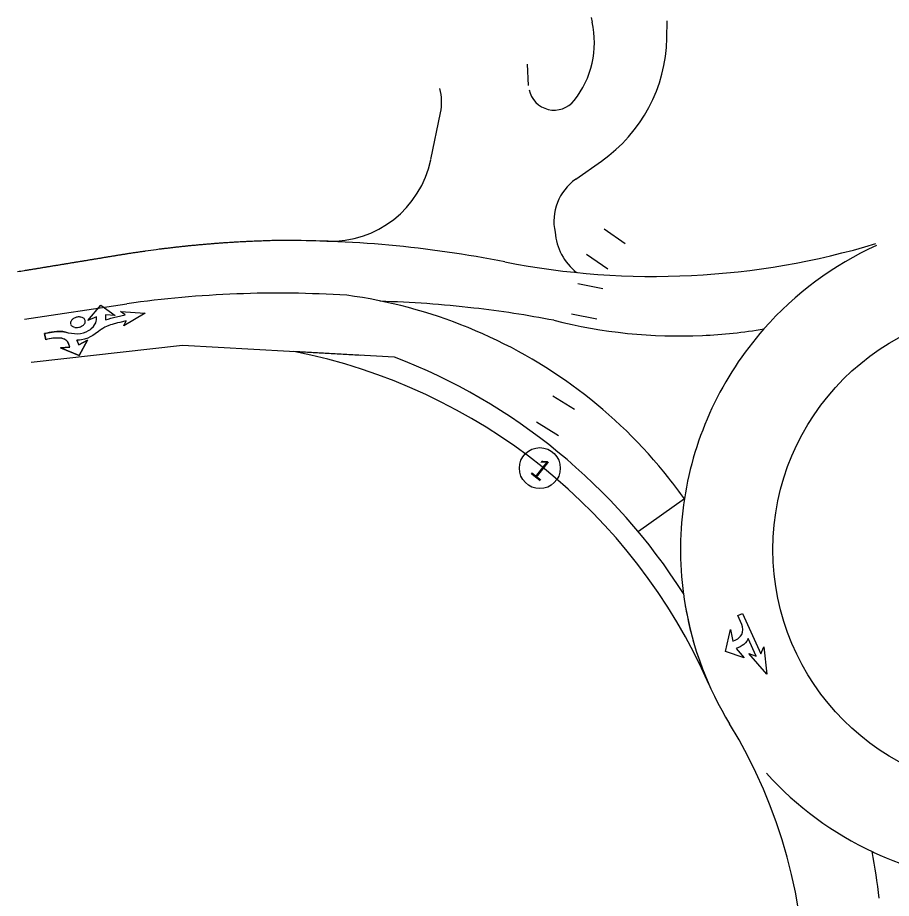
# Model space of a CAD drawing. Extents: x 553958 to 562499, y 493978 to 516388.
# Drawn here: x 561594.7 to 561765, y 497732.6 to 497904.2 of the extents above; entities that cross this region are included whole.
import ezdxf

# ---------------------------------------------------------------- set-up
doc = ezdxf.new("R2010")
doc.units = 0
for name, color, linetype in [('Exist Horizontal Alignment', 7, 'Continuous'), ('Prop Conc Shoulder Berm Gutter', 7, 'Continuous'), ('Prop Drainage Structure Gutter Shoulder Berm Label', 7, 'Continuous'), ('Prop DSN Text', 7, 'Continuous'), ('Prop EOT', 7, 'Continuous'), ('Prop Horizontal Alignment Tick Label', 7, 'Continuous'), ('Prop SS Cut Line', 7, 'Continuous'), ('Prop SS Fill Line', 7, 'Continuous'), ('Prop SS Transition Line', 7, 'Continuous'), ('Scratch_Level_4', 7, 'Continuous'), ('Sheet Plot Border Inside CELL', 7, 'Continuous'), ('Sheet Plot Border Outside CELL', 7, 'Continuous')]:
    doc.layers.add(name, color=color, linetype=linetype)

msp = doc.modelspace()

# ---------------------------------------------------------------- linework, layer by layer
at = {"layer": 'Exist Horizontal Alignment'}
msp.add_line((561597.34, 497837.09), (561626.82, 497840.36), dxfattribs=at)
msp.add_circle((561788.88, 497800.56), 47, dxfattribs=at)
msp.add_spline([(561619.61, 497858.68), (561619.59, 497858.67), (561618.91, 497858.58), (561618.23, 497858.48), (561617.55, 497858.38), (561616.87, 497858.27), (561616.19, 497858.17), (561615.51, 497858.06), (561614.83, 497857.95), (561614.17, 497857.85), (561613.52, 497857.74), (561612.87, 497857.63), (561612.22, 497857.52), (561611.57, 497857.42), (561610.93, 497857.31), (561610.28, 497857.2), (561609.63, 497857.1), (561608.98, 497856.99), (561608.33, 497856.88), (561607.68, 497856.78), (561607.03, 497856.67), (561606.38, 497856.56), (561605.73, 497856.46), (561605.09, 497856.35), (561604.44, 497856.24), (561603.79, 497856.14), (561603.14, 497856.03), (561602.49, 497855.92), (561601.84, 497855.82), (561601.19, 497855.71), (561600.54, 497855.6), (561599.9, 497855.5), (561599.25, 497855.39), (561598.6, 497855.28), (561597.95, 497855.18), (561597.3, 497855.07), (561596.65, 497854.96), (561596, 497854.86), (561594.71, 497854.64)], degree=3, dxfattribs=at)
at = {"layer": 'Prop Conc Shoulder Berm Gutter'}
msp.add_lwpolyline([(561724.64, 497810.44), (561715.66, 497804.08), (561715.66, 497804.08)], dxfattribs=at)
at = {"layer": 'Prop Drainage Structure Gutter Shoulder Berm Label'}
msp.add_lwpolyline([(561735.96, 497788.15), (561739.51, 497780.24), (561740.09, 497781.6), (561740.72, 497776.31), (561737.2, 497780.3), (561738.59, 497779.83), (561737.05, 497783.28), (561736.78, 497782.75), (561736.55, 497782.42), (561736.2, 497782.09), (561735.9, 497781.87), (561735.5, 497781.62), (561734.74, 497781.3), (561736.27, 497779.52), (561732.63, 497780.72), (561733.62, 497785), (561734.09, 497782.74), (561734.68, 497783.02), (561735.02, 497783.19), (561735.33, 497783.44), (561735.57, 497783.74), (561735.8, 497784.05), (561735.96, 497784.51), (561736.01, 497785.01), (561735.97, 497785.5), (561735.83, 497786.01), (561735.04, 497787.74)], close=True, dxfattribs=at)
msp.add_lwpolyline([(561735.96, 497788.15), (561739.51, 497780.24), (561740.09, 497781.6), (561740.72, 497776.31), (561737.2, 497780.3), (561738.59, 497779.83), (561737.05, 497783.28), (561736.78, 497782.75), (561736.55, 497782.42), (561736.2, 497782.09), (561735.9, 497781.87), (561735.5, 497781.62), (561734.74, 497781.3), (561736.27, 497779.52), (561732.63, 497780.72), (561733.62, 497785), (561734.09, 497782.74), (561734.68, 497783.02), (561735.02, 497783.19), (561735.33, 497783.44), (561735.57, 497783.74), (561735.8, 497784.05), (561735.96, 497784.51), (561736.01, 497785.01), (561735.97, 497785.5), (561735.83, 497786.01), (561735.04, 497787.74)], close=True, dxfattribs=at)
at = {"layer": 'Prop DSN Text'}
msp.add_circle((561696.46, 497816.43), 3.99, dxfattribs=at)
at = {"layer": 'Prop EOT'}
msp.add_lwpolyline([(561614.75, 497846.96), (561619.53, 497846.6), (561615.4, 497844.17), (561615.88, 497845.09), (561614.62, 497844.8), (561614.2, 497844.7), (561613.78, 497844.59), (561613.53, 497844.53), (561613.13, 497844.42), (561612.78, 497844.32), (561612.45, 497844.21), (561612.04, 497844.04), (561611.73, 497843.89), (561611.5, 497843.76), (561611.33, 497843.65), (561611.02, 497843.45), (561610.78, 497843.28), (561610.44, 497843.01), (561609.85, 497842.56), (561609.39, 497842.27), (561608.83, 497841.98), (561608.36, 497841.77), (561607.73, 497841.56), (561607.16, 497841.42), (561606.75, 497841.36), (561606.26, 497841.32), (561606.39, 497841.05), (561606.53, 497840.71), (561606.63, 497840.42), (561608.31, 497841.36), (561606.67, 497838.34), (561603.08, 497839.86), (561604.9, 497840.01), (561604.77, 497840.39), (561604.68, 497840.59), (561604.61, 497840.76), (561604.52, 497840.92), (561604.42, 497841.06), (561604.25, 497841.27), (561604.13, 497841.36), (561603.9, 497841.51), (561603.77, 497841.57), (561603.59, 497841.64), (561603.37, 497841.7), (561603.13, 497841.73), (561602.95, 497841.75), (561602.58, 497841.76), (561602.26, 497841.76), (561601.91, 497841.74), (561601.55, 497841.71), (561601.25, 497841.67), (561600.85, 497841.6), (561600.51, 497841.52), (561600.2, 497841.44), (561599.92, 497842.64), (561600.29, 497842.71), (561601.04, 497842.85), (561601.8, 497842.97), (561602.58, 497843.04), (561603.13, 497843.03), (561603.73, 497842.98), (561604.17, 497842.9), (561604.57, 497842.8), (561605.18, 497842.69), (561605.8, 497842.62), (561606.37, 497842.6), (561606.94, 497842.66), (561607.57, 497842.81), (561608.07, 497843), (561608.5, 497843.22), (561608.88, 497843.45), (561609, 497843.57), (561609.47, 497844.01), (561609.72, 497844.32), (561609.95, 497844.73), (561610.04, 497845.04), (561610.07, 497845.32), (561610.06, 497845.87), (561608.36, 497845.2), (561610.9, 497848.15), (561613.71, 497846.16), (561611.8, 497846.26), (561611.85, 497845.95), (561611.86, 497845.7), (561611.85, 497845.42), (561611.83, 497845.29), (561612.33, 497845.47), (561612.88, 497845.64), (561613.38, 497845.77), (561614, 497845.91), (561615.65, 497846.3)], close=True, dxfattribs=at)
for points in [[(561599.92, 497842.64), (561600.2, 497841.44)], [(561604.9, 497840.01), (561603.08, 497839.86), (561606.67, 497838.34), (561608.31, 497841.36), (561606.63, 497840.42)]]:
    msp.add_lwpolyline(points, dxfattribs=at)
for centre, radius, start, end in [((561606.31, 497844.35), 1.4, 125.8391, 148.5686), ((561606.67, 497843.85), 2.01, 117.8542, 125.8391), ((561606.71, 497843.77), 2.1, 105.1551, 117.8542), ((561606.68, 497843.89), 1.98, 103.1165, 105.1551), ((561606.68, 497843.89), 1.98, 101.0779, 103.1165), ((561606.7, 497843.77), 2.1, 88.3788, 101.0779), ((561606.7, 497843.86), 2.01, 80.3939, 88.3788), ((561606.8, 497844.46), 1.4, 57.6644, 80.3939), ((561607.14, 497844.99), 0.777, 37.4635, 57.6644), ((561607.17, 497845.01), 0.742, 14.3499, 37.4635), ((561605.74, 497844.68), 0.742, 168.7695, 191.8831), ((561605.78, 497844.67), 0.777, 148.5686, 168.7695), ((561605.62, 497844.65), 0.613, 191.8831, 193.1165), ((561605.62, 497844.65), 0.613, 193.1165, 194.3499), ((561605.74, 497844.68), 0.742, 194.3499, 217.4635), ((561605.77, 497844.71), 0.777, 217.4635, 237.6644), ((561606.1, 497845.23), 1.4, 237.6644, 260.3939), ((561606.2, 497845.83), 2.01, 260.3939, 268.3788), ((561606.21, 497845.93), 2.1, 268.3788, 281.0779), ((561606.23, 497845.81), 1.98, 281.0779, 283.1165), ((561606.23, 497845.81), 1.98, 283.1165, 285.1551), ((561606.2, 497845.93), 2.1, 285.1551, 297.8542), ((561606.24, 497845.84), 2.01, 297.8542, 305.8391), ((561606.6, 497845.35), 1.4, 305.8391, 328.5686), ((561607.13, 497845.02), 0.777, 328.5686, 348.7695), ((561607.29, 497845.04), 0.613, 13.1165, 14.3499), ((561607.29, 497845.04), 0.613, 11.8831, 13.1165), ((561607.16, 497845.02), 0.742, 348.7695, 11.8831), ((561604.82, 497820.46), 22.71, 97.5978, 102.4569), ((561602.8, 497835.83), 7.21, 79.8605, 97.8594), ((561607.45, 497855.36), 12.88, 254.8261, 257.1255), ((561602.47, 497833.53), 8.23, 85.4316, 106.0263), ((561602.96, 497839.67), 2.07, 67.0328, 85.2398), ((561603.02, 497839.85), 1.88, 50.3666, 66.5165), ((561602.87, 497839.91), 1.93, 22.6005, 45.6926), ((561600.14, 497838.55), 4.97, 16.9939, 25.0348), ((561601.16, 497838.74), 5.72, 17.1594, 26.8641)]:
    msp.add_arc(centre, radius, start, end, dxfattribs=at)
at = {"layer": 'Prop Horizontal Alignment Tick Label'}
for p, q in [((561706.44, 497904.16), (561706.64, 497903.3)), ((561721.23, 497900.14), (561721.3, 497903.51)), ((561694, 497895.12), (561694.19, 497890.94)), ((561675.22, 497876.5), (561677.12, 497885.6)), ((561703.45, 497872.68), (561708.5, 497876.24))]:
    msp.add_line(p, q, dxfattribs=at)
for centre, radius, start, end in [((561689.1, 497899.27), 18, 321.3714, 12.9457), ((561691.24, 497900.77), 30, 305.1307, 358.7969), ((561667.33, 497887.64), 10, 348.1958, 15.6669), ((561699.26, 497891.15), 5, 191.8074, 321.3714), ((561655.65, 497880.59), 20, 267.9632, 348.1958), ((561709.2, 497864.5), 10, 125.1307, 192.2367), ((561710.5, 497863.24), 11.1, 184.4316, 231.7557)]:
    msp.add_arc(centre, radius, start, end, dxfattribs=at)
at = {"layer": 'Prop SS Cut Line'}
for start, end in [(114.3559, 138.6093), (171.2574, 187.7029), (222.0826, 245.0549)]:
    msp.add_arc((561788.88, 497800.56), 65, start, end, dxfattribs=at)
at = {"layer": 'Prop SS Fill Line'}
msp.add_line((561668.11, 497838.07), (561648.52, 497839.16), dxfattribs=at)
for centre, radius, start, end in [((561626.87, 497729.27), 112, 23.753, 78.8587), ((561626.51, 497729.71), 116.07, 32.4541, 68.9929), ((561788.88, 497800.56), 65, 187.5698, 203.753)]:
    msp.add_arc(centre, radius, start, end, dxfattribs=at)
at = {"layer": 'Prop SS Transition Line'}
for centre, radius, start, end in [((561788.88, 497800.56), 65, 138.6093, 171.2574), ((561723.63, 497941.16), 99, 272.607, 279.589), ((561646.69, 497755.25), 95.5, 35.3031, 38.3255), ((561635.43, 497717.95), 128.01, 6.6088, 10.7165), ((561788.88, 497800.56), 65, 245.0024, 264.7081)]:
    msp.add_arc(centre, radius, start, end, dxfattribs=at)
at = {"layer": 'Scratch_Level_4'}
for p, q in [((561708.98, 497863.02), (561713.1, 497860.19)), ((561705.58, 497858.08), (561709.7, 497855.24)), ((561703.84, 497852.39), (561708.74, 497851.4)), ((561702.65, 497846.51), (561707.55, 497845.52)), ((561698.97, 497830.54), (561703.24, 497827.94)), ((561695.84, 497825.42), (561700.11, 497822.81))]:
    msp.add_line(p, q, dxfattribs=at)
at = {"layer": 'Sheet Plot Border Inside CELL'}
for p, q in [((561621.7, 497858.96), (561619.61, 497858.68)), ((561626.82, 497840.36), (561661.59, 497838.43))]:
    msp.add_line(p, q, dxfattribs=at)
for centre, radius, start, end in [((561647.12, 497640.75), 220, 87.9632, 90.7424), ((561647.12, 497640.75), 220, 78.8531, 90.7424), ((561647.12, 497640.75), 220, 87.8155, 87.9632), ((561718.65, 498003.77), 150, 258.8531, 286.7839), ((561659.47, 497638.78), 210.22, 79.109, 83.4141), ((561646.69, 497755.25), 95.5, 38.3255, 67.9911), ((561723.63, 497941.16), 99, 255.7113, 272.607), ((561626.87, 497729.27), 112, 23.753, 78.8587), ((561788.88, 497800.56), 65, 189.695, 211.483), ((561648.17, 497714.39), 100, 327.065, 31.483)]:
    msp.add_arc(centre, radius, start, end, dxfattribs=at)
msp.add_spline([(561644.27, 497860.73), (561643.58, 497860.71), (561642.89, 497860.69), (561642.2, 497860.66), (561641.51, 497860.64), (561640.83, 497860.61), (561640.14, 497860.58), (561639.45, 497860.55), (561638.76, 497860.51), (561638.07, 497860.48), (561637.39, 497860.44), (561636.7, 497860.4), (561636.01, 497860.35), (561635.33, 497860.31), (561634.64, 497860.26), (561633.95, 497860.21), (561633.27, 497860.16), (561632.58, 497860.1), (561631.89, 497860.05), (561631.21, 497859.99), (561630.52, 497859.93), (561629.84, 497859.87), (561629.15, 497859.8), (561628.47, 497859.74), (561627.78, 497859.67), (561627.1, 497859.6), (561626.41, 497859.52), (561625.73, 497859.45), (561625.05, 497859.37), (561624.36, 497859.29), (561623.68, 497859.21), (561623, 497859.13), (561622.31, 497859.04), (561621.7, 497858.96)], degree=3, dxfattribs=at)
at = {"layer": 'Sheet Plot Border Outside CELL'}
msp.add_line((561596.08, 497845.44), (561616.01, 497848.43), dxfattribs=at)
for centre, radius, start, end in [((561645.49, 497640.75), 209.76, 86.346, 98.0799), ((561646.13, 497754.78), 96.15, 67.786, 82.3961), ((561659.47, 497638.78), 210.22, 83.4141, 88.4115)]:
    msp.add_arc(centre, radius, start, end, dxfattribs=at)

# ---------------------------------------------------------------- texts
at = {"layer": 'Prop EOT'}
msp.add_text('1', height=4, rotation=321.6667, dxfattribs=at).set_placement((561694.34, 497815.55))

doc.saveas('drawing.dxf')
